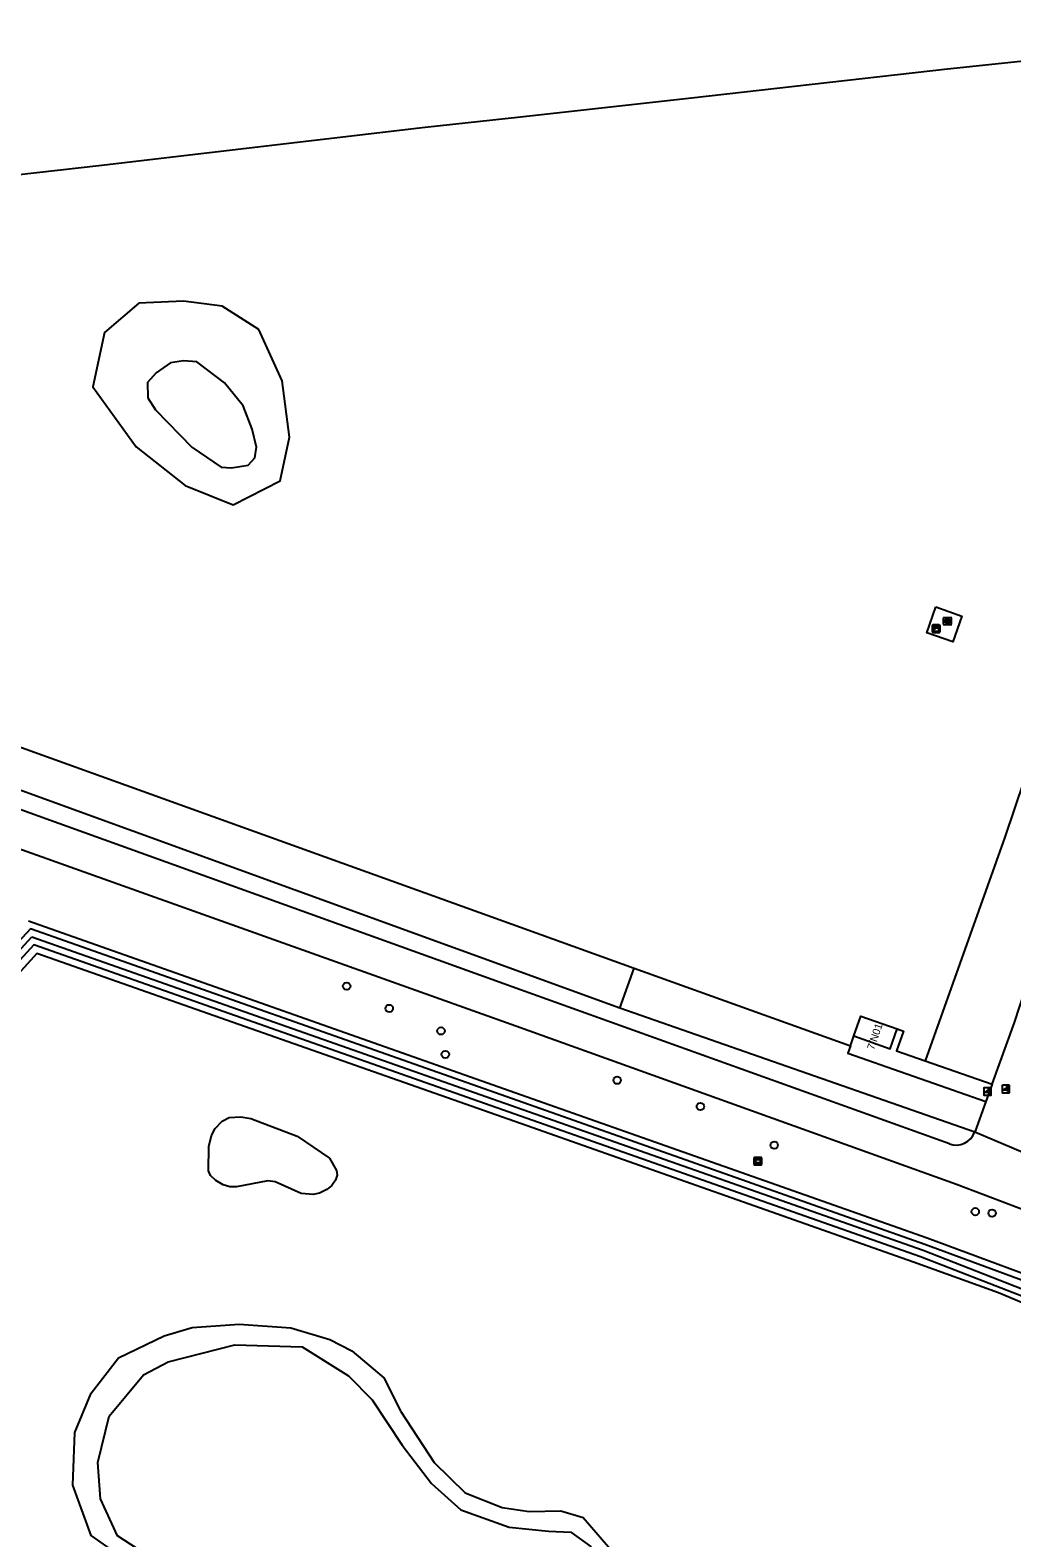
# Model space of a CAD drawing. Extents: x 156061 to 157804, y 383451 to 385640.
# Drawn here: x 156435.3 to 156564.9, y 385038.4 to 385237.5 of the extents above; entities that cross this region are included whole.
import ezdxf

# ---------------------------------------------------------------- set-up
doc = ezdxf.new("R2010")
doc.units = 0
for name, color, linetype in [('IMGEO_Boom', 7, 'Continuous'), ('IMGEO_Grasland_overig', 7, 'Continuous'), ('IMGEO_Groenvoorziening', 7, 'Continuous'), ('IMGEO_Kast', 7, 'Continuous'), ('IMGEO_Meer_plas_ven_vijver', 7, 'Continuous'), ('IMGEO_Pand', 7, 'Continuous'), ('IMGEO_Pand_nummerreeks', 7, 'Continuous'), ('IMGEO_Poller', 7, 'Continuous'), ('IMGEO_Rijbaan_lokaal_gesloten', 7, 'Continuous'), ('IMGEO_Rioolput', 7, 'Continuous'), ('IMGEO_Verklikker', 7, 'Continuous'), ('IMGEO_Voetpad_open', 7, 'Continuous'), ('IMGEO_Waterloop', 7, 'Continuous')]:
    doc.layers.add(name, color=color, linetype=linetype)

msp = doc.modelspace()

# ---------------------------------------------------------------- linework, layer by layer
at = {"layer": 'IMGEO_Boom'}
for centre in [(156477.05, 385111.22), (156482.67, 385108.28), (156489.5, 385105.3), (156490.07, 385102.2), (156512.75, 385098.79), (156523.74, 385095.32), (156533.49, 385090.22), (156560.03, 385081.44), (156562.25, 385081.23)]:
    msp.add_circle(centre, 0.489, dxfattribs=at)
at = {"layer": 'IMGEO_Grasland_overig'}
for points in [[(156513.09, 385108.31), (156319.71, 385178.59)], [(156559.95, 385091.94), (156513.09, 385108.31)]]:
    msp.add_lwpolyline(points, dxfattribs=at)
at = {"layer": 'IMGEO_Groenvoorziening'}
for points in [[(156604.54, 385237.46), (156602.37, 385235.01), (156599.58, 385231.31), (156597.17, 385226.55), (156595.13, 385221.87), (156592.88, 385215.94), (156590.35, 385208.6), (156585.87, 385195.59), (156576.52, 385168.23), (156563.92, 385130.88), (156553.4, 385101.35)], [(156397.01, 385215.36), (156407.76, 385215.44), (156417.02, 385216.5), (156444.32, 385219.59), (156487.42, 385224.63), (156500, 385226.03), (156522.58, 385228.54), (156556.36, 385232.36), (156590.31, 385235.94)], [(156465.44, 385197.95), (156460.59, 385201.02), (156455.49, 385201.67), (156449.59, 385201.42), (156445.06, 385197.54), (156443.53, 385190.34), (156449.27, 385182.42), (156455.74, 385177.32), (156462.07, 385174.79), (156468.25, 385177.95), (156469.51, 385183.71), (156468.51, 385191.15), (156465.44, 385197.95)], [(156327.27, 385181.21), (156500, 385119), (156514.99, 385113.6)], [(156554.83, 385161.29), (156558.24, 385160.09), (156557.05, 385156.68), (156553.63, 385157.88), (156554.83, 385161.29)], [(156435.06, 385119.83), (156500, 385096.91), (156553.67, 385077.98), (156566.96, 385073.06), (156570.74, 385071.38)], [(156567.98, 385069.56), (156552.81, 385075.49), (156500, 385094.07), (156435.74, 385116.68), (156396.11, 385073.31)], [(156704.18, 384910.35), (156680.54, 384938.81), (156675.71, 384944.62), (156664.3, 384958.48), (156630.11, 385000), (156603.33, 385032.02), (156590.03, 385048.18), (156581.38, 385058.42), (156579.11, 385060.99), (156576.25, 385063.65), (156574.17, 385065.13), (156572.59, 385066.26), (156568.65, 385068.4), (156563.11, 385070.71), (156551.89, 385074.79), (156500, 385093.06), (156436.13, 385115.54), (156397.25, 385072.57), (156397.42, 385071.83)], [(156513.09, 385108.31), (156514.99, 385113.6)], [(156514.99, 385113.6), (156543.55, 385103.32)], [(156467.59, 385085.38), (156466.64, 385085.51), (156462.5, 385084.7), (156461.61, 385084.72), (156460.74, 385084.97), (156459.76, 385085.57), (156459.09, 385086.23), (156458.8, 385086.82), (156458.86, 385090.03), (156459.2, 385091.48), (156459.68, 385092.44), (156460.61, 385093.4), (156461.52, 385093.88), (156463.07, 385093.96), (156464.4, 385093.76), (156470.5, 385091.4), (156474.77, 385088.49), (156475.71, 385086.87), (156475.79, 385086.24), (156475.58, 385085.6), (156475.1, 385084.88), (156474.45, 385084.35), (156473.46, 385083.89), (156472.62, 385083.71), (156471.03, 385083.82), (156467.59, 385085.38)], [(156450.69, 385033.47), (156443.31, 385038.67), (156440.92, 385045.34), (156441.18, 385052.27), (156443.31, 385057.47), (156446.91, 385062.13), (156452.97, 385065.06), (156456.67, 385066.14), (156462.87, 385066.57), (156469.69, 385066.1), (156474.84, 385064.56), (156477.72, 385063.05), (156481.96, 385059.51), (156484.21, 385055.04), (156488.59, 385048.33), (156492.69, 385044.29), (156497.57, 385042.36), (156501.12, 385041.85), (156505.33, 385041.94), (156508.27, 385041.06), (156512.45, 385036.2)]]:
    msp.add_lwpolyline(points, dxfattribs=at)
at = {"layer": 'IMGEO_Kast'}
for p, q in [((156554.37, 385158), (156554.37, 385158.84)), ((156554.37, 385158.84), (156554.37, 385158)), ((156554.44, 385158.93), (156555.28, 385158.93)), ((156555.28, 385158.93), (156554.44, 385158.93)), ((156555.37, 385158.85), (156555.37, 385158.01)), ((156555.37, 385158.01), (156555.37, 385158.85)), ((156555.29, 385157.93), (156554.45, 385157.93)), ((156554.45, 385157.93), (156555.29, 385157.93))]:
    msp.add_line(p, q, dxfattribs=at)
for points in [[(156554.56, 385158.72), (156555.16, 385158.72), (156555.16, 385158.63), (156554.56, 385158.63), (156554.56, 385158.72)], [(156554.56, 385158.54), (156555.16, 385158.54), (156555.16, 385158.05), (156554.56, 385158.05), (156554.56, 385158.54)]]:
    msp.add_lwpolyline(points, dxfattribs=at)
msp.add_circle((156554.65, 385158.39), 0.0377, dxfattribs=at)
for centre, start, end in [((156554.45, 385158.85), 92.4484, 184.2845), ((156554.45, 385158.85), 92.4484, 184.2845), ((156555.29, 385158.85), 2.4484, 94.2845), ((156555.29, 385158.85), 2.4484, 94.2845), ((156554.45, 385158.01), 182.4484, 274.2845), ((156554.45, 385158.01), 182.4484, 274.2845), ((156555.29, 385158.01), 272.4484, 4.2845), ((156555.29, 385158.01), 272.4484, 4.2845)]:
    msp.add_arc(centre, 0.0779, start, end, dxfattribs=at)
at = {"layer": 'IMGEO_Meer_plas_ven_vijver'}
for points in [[(156464.05, 385180.01), (156464.93, 385180.98), (156465.14, 385182.41), (156464.59, 385184.76), (156463.37, 385187.87), (156460.93, 385190.9), (156457.27, 385193.67), (156455.51, 385193.8), (156453.79, 385193.51), (156451.89, 385192.2), (156450.76, 385190.94), (156450.8, 385188.92), (156451.81, 385187.33), (156456.6, 385182.41), (156460.47, 385179.76), (156461.86, 385179.67), (156464.05, 385180.01)], [(156445.68, 385054.45), (156450.21, 385059.87), (156453.5, 385061.59), (156462.27, 385063.85), (156471.19, 385063.57), (156477.31, 385059.75), (156480.43, 385056.57), (156484.39, 385050.6), (156488.26, 385045.55), (156492.12, 385042.07), (156498.5, 385039.79), (156503.69, 385039.25), (156506.63, 385039.12), (156509.32, 385037.19)], [(156451.95, 385035.27), (156446.78, 385038.64), (156444.55, 385043.52), (156444.22, 385048.3), (156445.68, 385054.45)]]:
    msp.add_lwpolyline(points, dxfattribs=at)
at = {"layer": 'IMGEO_Pand'}
for points in [[(156544.01, 385104.64), (156544.92, 385107.25), (156549.72, 385105.57)], [(156544.01, 385104.64), (156548.8, 385102.96), (156549.72, 385105.57)]]:
    msp.add_lwpolyline(points, dxfattribs=at)
at = {"layer": 'IMGEO_Poller'}
for p, q in [((156561.14, 385097.71), (156561.14, 385096.9)), ((156561.14, 385097.71), (156561.14, 385096.9)), ((156562.04, 385097.81), (156561.23, 385097.81)), ((156562.04, 385097.81), (156561.23, 385097.81)), ((156562.13, 385096.9), (156562.13, 385097.71)), ((156562.13, 385096.9), (156562.13, 385097.71)), ((156563.56, 385098.02), (156563.56, 385097.22)), ((156563.56, 385098.02), (156563.56, 385097.22)), ((156564.46, 385098.12), (156563.65, 385098.12)), ((156564.46, 385098.12), (156563.65, 385098.12)), ((156563.65, 385097.12), (156564.46, 385097.12)), ((156563.65, 385097.12), (156564.46, 385097.12)), ((156564.55, 385097.22), (156564.55, 385098.02)), ((156564.55, 385097.22), (156564.55, 385098.02)), ((156561.23, 385096.81), (156562.04, 385096.81)), ((156561.23, 385096.81), (156562.04, 385096.81))]:
    msp.add_line(p, q, dxfattribs=at)
for points in [[(156561.77, 385097.16), (156561.26, 385097.16), (156561.69, 385097.44)], [(156561.82, 385097.54), (156561.8, 385097.46), (156561.68, 385097.67)], [(156561.68, 385097.67), (156561.91, 385097.6), (156561.84, 385097.57)], [(156561.83, 385096.99), (156561.9, 385097.22), (156561.93, 385097.15)], [(156561.97, 385097.13), (156562.04, 385097.12), (156561.83, 385096.99)], [(156564.19, 385097.48), (156563.68, 385097.48), (156564.11, 385097.75)], [(156564.23, 385097.85), (156564.22, 385097.78), (156564.1, 385097.98)], [(156564.1, 385097.98), (156564.33, 385097.91), (156564.26, 385097.88)], [(156564.25, 385097.3), (156564.32, 385097.53), (156564.35, 385097.47)], [(156564.38, 385097.44), (156564.46, 385097.43), (156564.25, 385097.3)]]:
    msp.add_lwpolyline(points, dxfattribs=at)
for centre, radius, start, end in [((156561.23, 385097.71), 0.0946, 90, 180), ((156561.23, 385097.71), 0.0946, 90, 180), ((156561.44, 385097.21), 0.332, 351.3247, 42.4854), ((156561.46, 385097.22), 0.476, 351.7527, 41.1691), ((156561.46, 385097.22), 0.516, 349.3569, 42.2912), ((156562.04, 385097.71), 0.0946, 0, 90), ((156562.04, 385097.71), 0.0946, 0, 90), ((156563.65, 385098.02), 0.0946, 90, 180), ((156563.65, 385098.02), 0.0946, 90, 180), ((156563.65, 385097.22), 0.0946, 180, 270), ((156563.65, 385097.22), 0.0946, 180, 270), ((156563.86, 385097.53), 0.332, 351.3247, 42.4854), ((156563.88, 385097.53), 0.476, 351.7527, 41.1691), ((156563.88, 385097.53), 0.516, 349.3569, 42.2912), ((156564.46, 385098.02), 0.0946, 0, 90), ((156564.46, 385098.02), 0.0946, 0, 90), ((156564.46, 385097.22), 0.0946, 270, 0), ((156564.46, 385097.22), 0.0946, 270, 0), ((156561.23, 385096.9), 0.0946, 180, 270), ((156561.23, 385096.9), 0.0946, 180, 270), ((156562.04, 385096.9), 0.0946, 270, 0), ((156562.04, 385096.9), 0.0946, 270, 0)]:
    msp.add_arc(centre, radius, start, end, dxfattribs=at)
at = {"layer": 'IMGEO_Rijbaan_lokaal_gesloten'}
for points in [[(156562.24, 385098.26), (156565.2, 385106.42), (156577.76, 385144.83), (156586.71, 385170.27), (156596.08, 385197.94), (156601.08, 385213.63), (156602.54, 385217.74)], [(156556.61, 385090.38), (156500, 385110.73), (156337.29, 385169.36), (156325.8, 385173.38)], [(156324.12, 385168.82), (156326.22, 385167.86), (156431.78, 385130.12), (156500, 385105.74), (156557.53, 385085.07), (156567.97, 385081.12), (156578.06, 385077.45), (156590.93, 385073.63)], [(156562.24, 385098.26), (156561.42, 385096)], [(156561.42, 385096), (156559.95, 385091.94)], [(156566.3, 385089.23), (156559.95, 385091.94)]]:
    msp.add_lwpolyline(points, dxfattribs=at)
msp.add_arc((156557.5, 385092.83), 2.6, 250.2028, 340.1, dxfattribs=at)
at = {"layer": 'IMGEO_Rioolput'}
for p, q in [((156555.85, 385159), (156555.85, 385159.85)), ((156555.93, 385159.92), (156556.78, 385159.92)), ((156556.78, 385158.92), (156555.93, 385158.92)), ((156556.34, 385159.7), (156556.37, 385159.7)), ((156556.36, 385159.14), (156556.34, 385159.14)), ((156556.85, 385159.85), (156556.85, 385159))]:
    msp.add_line(p, q, dxfattribs=at)
for points in [[(156555.85, 385159), (156555.85, 385159.85)], [(156555.93, 385159.92), (156556.78, 385159.92)], [(156556.78, 385158.92), (156555.93, 385158.92)], [(156556.44, 385159.62), (156556.19, 385159.62), (156556.19, 385159.22)], [(156556.19, 385159.22), (156556.31, 385159.22), (156556.31, 385159.39), (156556.32, 385159.39)], [(156556.37, 385159.54), (156556.31, 385159.54), (156556.31, 385159.46)], [(156556.31, 385159.46), (156556.36, 385159.46)], [(156556.37, 385159.36), (156556.44, 385159.22), (156556.58, 385159.22), (156556.52, 385159.35)], [(156556.85, 385159.85), (156556.85, 385159)]]:
    msp.add_lwpolyline(points, dxfattribs=at)
for centre, radius, start, end in [((156555.93, 385159.85), 0.0765, 91.552, 178.448), ((156555.93, 385159.85), 0.0765, 91.552, 178.448), ((156555.93, 385159), 0.0765, 181.552, 268.448), ((156555.93, 385159), 0.0765, 181.552, 268.448), ((156556.32, 385159.33), 0.0533, 26.0293, 88.6989), ((156556.35, 385159.65), 0.19, 274.7715, 282.9687), ((156556.37, 385159.45), 0.0964, 77.0061, 93.1865), ((156556.39, 385159.5), 0.0378, 276.6634, 79.6772), ((156556.44, 385159.51), 0.109, 350.3612, 89.416), ((156556.44, 385159.51), 0.112, 277.5842, 350.9817), ((156556.42, 385159.3), 0.108, 29.5134, 73.7905), ((156556.78, 385159.85), 0.0765, 1.552, 88.448), ((156556.78, 385159.85), 0.0765, 1.552, 88.448), ((156556.78, 385159), 0.0765, 271.552, 358.448), ((156556.78, 385159), 0.0765, 271.552, 358.448)]:
    msp.add_arc(centre, radius, start, end, dxfattribs=at)
for centre, major_axis, ratio, start_param, end_param in [((156556.34, 385159.42), (-0.387, 0.002), 0.722429, 4.712389, 7.853982), ((156556.36, 385159.42), (-0.39, 0.002), 0.717154, 1.570796, 4.712389)]:
    msp.add_ellipse(centre, major_axis=major_axis, ratio=ratio, start_param=start_param, end_param=end_param, dxfattribs=at)
at = {"layer": 'IMGEO_Verklikker'}
for p, q in [((156530.83, 385087.71), (156530.83, 385088.51)), ((156530.83, 385088.51), (156530.83, 385087.71)), ((156530.93, 385088.61), (156531.72, 385088.61)), ((156531.72, 385088.61), (156530.93, 385088.61)), ((156531.72, 385087.61), (156530.93, 385087.61)), ((156530.93, 385087.61), (156531.72, 385087.61)), ((156531.82, 385088.51), (156531.82, 385087.71)), ((156531.82, 385087.71), (156531.82, 385088.51))]:
    msp.add_line(p, q, dxfattribs=at)
for points in [[(156530.93, 385088.34), (156531.72, 385088.34), (156531.72, 385087.88), (156530.93, 385087.88), (156530.93, 385088.34)], [(156531, 385088.28), (156531, 385087.94), (156531.66, 385087.94), (156531.66, 385088.28), (156531, 385088.28)]]:
    msp.add_lwpolyline(points, dxfattribs=at)
for centre, start, end in [((156530.93, 385088.51), 90, 180), ((156530.93, 385088.51), 90, 180), ((156530.93, 385087.71), 180, 270), ((156530.93, 385087.71), 180, 270), ((156531.72, 385088.51), 0, 90), ((156531.72, 385088.51), 360, 90), ((156531.72, 385087.71), 270, 0), ((156531.72, 385087.71), 270, 0)]:
    msp.add_arc(centre, 0.1, start, end, dxfattribs=at)
at = {"layer": 'IMGEO_Voetpad_open'}
for points in [[(156549.72, 385105.57), (156550.57, 385105.27), (156549.65, 385102.67), (156553.4, 385101.35)], [(156543.55, 385103.32), (156543.22, 385102.38), (156561.42, 385096)], [(156543.55, 385103.32), (156544.01, 385104.64)], [(156553.4, 385101.35), (156562.24, 385098.26)]]:
    msp.add_lwpolyline(points, dxfattribs=at)
at = {"layer": 'IMGEO_Waterloop'}
for points in [[(156566.62, 385072.22), (156553.36, 385077.12), (156499.7, 385096.06), (156435.32, 385118.78), (156395.22, 385075.54), (156396.1, 385074.63), (156435.47, 385117.74)], [(156435.47, 385117.74), (156500.3, 385094.93), (156553.13, 385076.34), (156568.31, 385070.4)]]:
    msp.add_lwpolyline(points, dxfattribs=at)

# ---------------------------------------------------------------- texts
at = {"layer": 'IMGEO_Pand_nummerreeks'}
msp.add_text('7/N01', height=1, rotation=71.2171, dxfattribs=at).set_placement((156546.66, 385102.72))

doc.saveas('drawing.dxf')
